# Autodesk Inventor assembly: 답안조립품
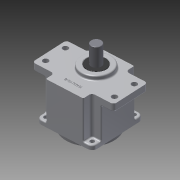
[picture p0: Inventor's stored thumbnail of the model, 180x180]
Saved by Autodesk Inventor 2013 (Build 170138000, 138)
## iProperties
Created: 2015-07
Part Number: 답안조립품
Document SubType Name: Assembly
Designer: user
Author: user
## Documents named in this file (12)
- C:\Users\user\Desktop\450734V1025\답안조립품.iam
- C:\Users\user\Desktop\450734V1025\메인축.ipt
- C:\Users\user\Desktop\450734V1025\베어링 6003.ipt
- 베어링 6003.ipt
- C:\Users\user\Desktop\450734V1025\베어링 608.ipt
- 베어링 608.ipt
- C:\Users\user\Desktop\450734V1025\서브축.ipt
- C:\Users\user\Desktop\450734V1025\본체.ipt
- C:\Users\user\Desktop\450734V1025\커버.ipt
- C:\Users\user\Desktop\450734V1025\오일실 8x22x7.ipt
- C:\Users\user\Desktop\450734V1025\오일실 17x32x8.ipt
- C:\Users\user\Desktop\450734V1025\M4x0.5x16.ipt
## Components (4 placed, 1 different names)
1. M4x0.5x12:1
2. M4x0.5x12:2
3. M4x0.5x12:3
4. M4x0.5x12:4
